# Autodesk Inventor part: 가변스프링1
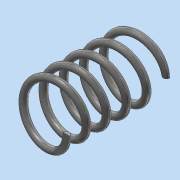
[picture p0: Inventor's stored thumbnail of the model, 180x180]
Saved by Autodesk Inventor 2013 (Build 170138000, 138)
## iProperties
Created: 2018-10
Part Number: 가변스프링1
Material: 스테인리스강
Document SubType Name: Modeling
Designer: Administrator
Density: 1 g/cm^3
Mass: 0.77701 g
Surface Area: 15.7902 cm^2
Volume: 0.77701 cm^3
Author: Administrator
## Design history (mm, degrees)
sketch "스케치1"
  geometry: L1 (0, 0)-(0, -30.473); L2 (8, 0)-(0, 0); L3 (0, -30.473)-(8, -30.473); C1 r 1 at (8, 0)
  constraints: 6 end point, 1 centre point, 1 horizontal alignment, 1 parallel, 1 perpendicular, 1 vertical
  dimensions: "d0" = 30.47293 distance of L1.start L1.end (derived); "d1" = 2 diameter of C1; "d2" = 16 diameter of L2.start L1; "d3" = 8 distance of L1.end L3.end
feature "코일1" sketch "스케치1" pitch "d4" = 10; turns "d6" = 5; dims "d5" = 30.47293 (= d0), "d7" = 0, angle "d8" = 90 deg, angle "d9" = 90 deg, "d10" = 0, "d11" = 0
sketch "스케치2"
  geometry: L1 (-30.473, 10)-(0, 10); L2 (0, 10)-(0, -10); L3 (0, -10)-(-30.473, -10); L4 (-30.473, -10)-(-30.473, 10); 2 further points
  constraints: 8 end point, 2 parallel, 1 coincident, 1 horizontal, 1 midpoint, 1 perpendicular
  dimensions: "d12" = 30.47293 distance of L2.end L3.end (derived); "d14" = 20 distance of L1.end L2.end
extrude "돌출1" sketch "스케치2" stored distance "d15" = 0; taper "d16" = 0 deg
node "솔리드1"
